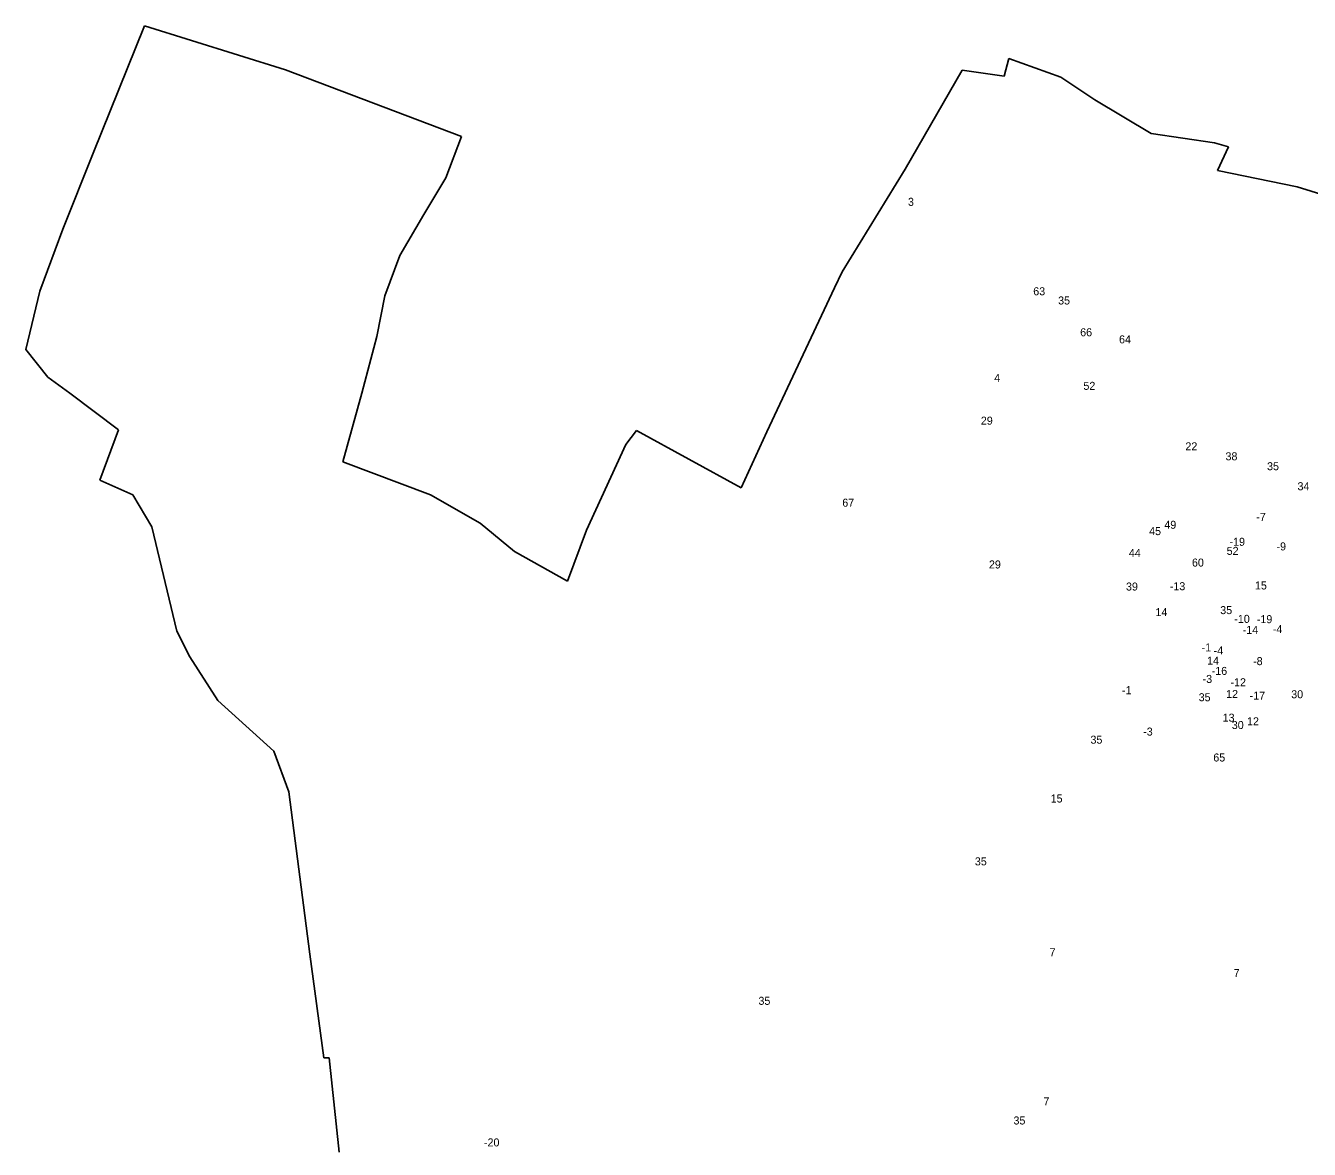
# Model space of a CAD drawing. Extents: x -780076 to -778282, y -991307 to -989717.
# Drawn here: x -780076 to -779194, y -990547 to -989775 of the extents above; entities that cross this region are included whole.
import ezdxf

# ---------------------------------------------------------------- set-up
doc = ezdxf.new("R2010")
doc.units = 0
doc.layers.add('Vrstva 13', color=7, linetype='Continuous')
doc.layers.add('Vrstva 24', color=7, linetype='Continuous')

msp = doc.modelspace()

# ---------------------------------------------------------------- linework, layer by layer
at = {"layer": 'Vrstva 13'}
for p, q in [((-779994.14, -989774.6), (-780029.22, -989862.28)), ((-779994.14, -989774.6), (-779897.12, -989805)), ((-779403.36, -989809.22), (-779399.96, -989797.26)), ((-779399.96, -989797.26), (-779364.42, -989810.09)), ((-779897.12, -989805), (-779776.11, -989850.64)), ((-779471.37, -989873.15), (-779432.11, -989805.18)), ((-779432.11, -989805.18), (-779403.36, -989809.22)), ((-779364.42, -989810.09), (-779340.88, -989825.61)), ((-779340.88, -989825.61), (-779302.27, -989848.62)), ((-779776.11, -989850.64), (-779787.07, -989879.21)), ((-779302.27, -989848.62), (-779258.78, -989855.1)), ((-779258.78, -989855.1), (-779249.09, -989857.81)), ((-779249.09, -989857.81), (-779256.69, -989874.15)), ((-780029.22, -989862.28), (-780050.08, -989914.47)), ((-779514.52, -989943.79), (-779471.37, -989873.15)), ((-779256.69, -989874.15), (-779201.85, -989885.24)), ((-779787.07, -989879.21), (-779802.07, -989904.26)), ((-779201.85, -989885.24), (-779176.1, -989893.26)), ((-779802.07, -989904.26), (-779818.63, -989932.43)), ((-780050.08, -989914.47), (-780065.86, -989957)), ((-779818.63, -989932.43), (-779828.8, -989960.22)), ((-779519.81, -989954.82), (-779514.52, -989943.79)), ((-780065.86, -989957), (-780075.7, -989996.99)), ((-779566.42, -990053.75), (-779519.81, -989954.82)), ((-779828.8, -989960.22), (-779834.27, -989988.26)), ((-779834.27, -989988.26), (-779844.7, -990027.01)), ((-780075.7, -989996.99), (-780060.51, -990016.1)), ((-780060.51, -990016.1), (-780045.31, -990027.19)), ((-780045.31, -990027.19), (-780011.93, -990052.24)), ((-779844.7, -990027.01), (-779857.73, -990074.23)), ((-780011.93, -990052.24), (-780024.64, -990086.81)), ((-779663.17, -990062.29), (-779655.94, -990052.64)), ((-779655.94, -990052.64), (-779583.96, -990092.1)), ((-779583.96, -990092.1), (-779566.42, -990053.75)), ((-779690.3, -990121.19), (-779663.17, -990062.29)), ((-779857.73, -990074.23), (-779797.49, -990096.93)), ((-780024.64, -990086.81), (-780002.08, -990096.86)), ((-780002.08, -990096.86), (-779988.97, -990119.04)), ((-779797.49, -990096.93), (-779763.33, -990116.5)), ((-779988.97, -990119.04), (-779971.83, -990190.67)), ((-779763.33, -990116.5), (-779739.72, -990135.81)), ((-779703.34, -990156.16), (-779690.3, -990121.19)), ((-779739.72, -990135.81), (-779703.34, -990156.16)), ((-779971.83, -990190.67), (-779962.83, -990208.15)), ((-779962.83, -990208.15), (-779943.66, -990238.29)), ((-779943.66, -990238.29), (-779905.06, -990273.12)), ((-779905.06, -990273.12), (-779894.95, -990301.04)), ((-779894.95, -990301.04), (-779880.53, -990412.59)), ((-779880.53, -990412.59), (-779870.77, -990483.71)), ((-779870.77, -990483.71), (-779867.24, -990483.81)), ((-779860.19, -990548.54), (-779867.24, -990483.81))]:
    msp.add_line(p, q, dxfattribs=at)

# ---------------------------------------------------------------- texts
at = {"layer": 'Vrstva 24'}
for s, p in [('3', (-779469.36, -989898.37)), ('63', (-779383.28, -989959.83)), ('35', (-779366.18, -989966.16)), ('66', (-779351.02, -989988)), ('64', (-779324.31, -989992.87)), ('4', (-779410.1, -990019.34)), ('52', (-779348.81, -990024.81)), ('29', (-779419.28, -990048.74)), ('22', (-779278.71, -990066.37)), ('38', (-779251.15, -990073.22)), ('35', (-779222.58, -990080.03)), ('34', (-779201.67, -990093.79)), ('67', (-779514.502, -990105.08)), ('49', (-779293.19, -990120.26)), ('-7', (-779229.993, -990114.88)), ('45', (-779303.64, -990124.62)), ('52', (-779250.35, -990138.19)), ('-19', (-779248.39, -990131.95)), ('-9', (-779216.102, -990135.13)), ('29', (-779413.73, -990147.53)), ('44', (-779317.55, -990139.58)), ('60', (-779274.198, -990146.23)), ('39', (-779319.54, -990162.7)), ('-13', (-779289.431, -990162.48)), ('15', (-779230.89, -990161.95)), ('14', (-779299.289, -990180.26)), ('35', (-779254.78, -990178.9)), ('-10', (-779245.119, -990184.91)), ('-14', (-779239.33, -990192.45)), ('-19', (-779229.64, -990185.11)), ('-4', (-779218.642, -990191.96)), ('-1', (-779267.581, -990204.55)), ('-4', (-779259.282, -990206.63)), ('14', (-779263.799, -990213.59)), ('-8', (-779232.192, -990213.97)), ('-3', (-779266.892, -990226.17)), ('-16', (-779260.64, -990220.66)), ('-1', (-779322.301, -990233.9)), ('12', (-779250.74, -990236.54)), ('-12', (-779247.721, -990228.45)), ('35', (-779269.59, -990238.76)), ('-17', (-779234.562, -990237.67)), ('30', (-779205.988, -990236.72)), ('13', (-779253.12, -990252.8)), ('-3', (-779307.732, -990262.36)), ('30', (-779246.838, -990257.84)), ('12', (-779236.36, -990255.27)), ('35', (-779343.95, -990267.92)), ('65', (-779259.53, -990280.16)), ('15', (-779371.29, -990308.33)), ('35', (-779423.41, -990351.53)), ('7', (-779372.072, -990413.98)), ('7', (-779245.562, -990428.26)), ('35', (-779572.13, -990447.34)), ('7', (-779376.282, -990516.46)), ('35', (-779396.86, -990529.55)), ('-20', (-779760.75, -990544.62))]:
    msp.add_text(s, height=5.5, dxfattribs=at).set_placement(p)

doc.saveas('drawing.dxf')
